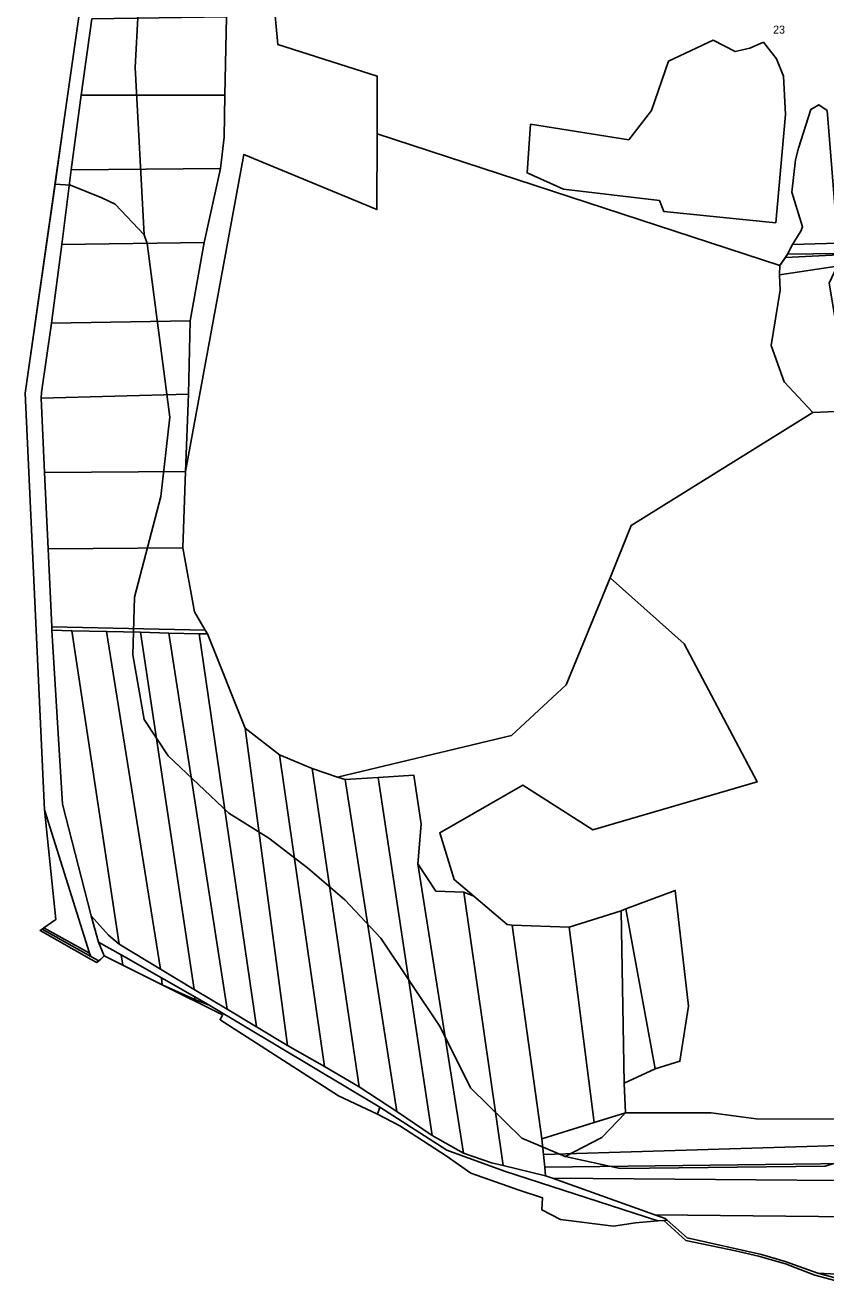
# Model space of a CAD drawing. Extents: x -521261 to -517465, y -1182764 to -1179456.
# Drawn here: x -521261 to -520761, y -1181677 to -1180889 of the extents above; entities that cross this region are included whole.
import ezdxf

# ---------------------------------------------------------------- set-up
doc = ezdxf.new("R2010")
doc.units = 0
for name, color, linetype in [('95560013', 7, 'Continuous'), ('95610013', 7, 'Continuous'), ('95620013', 7, 'Continuous'), ('95640013', 7, 'Continuous'), ('95660013', 7, 'Continuous')]:
    doc.layers.add(name, color=color, linetype=linetype)

msp = doc.modelspace()

# ---------------------------------------------------------------- linework, layer by layer
at = {"layer": '95560013'}
for points in [[(-521219.69, -1180885.08), (-521135.49, -1180884), (-521136.51, -1180932.9), (-521226.29, -1180932.9)], [(-521226.29, -1180932.9), (-521136.51, -1180932.9), (-521137.03, -1180959.08), (-521139.18, -1180978.59), (-521232.52, -1180979.52)], [(-521232.52, -1180979.52), (-521139.18, -1180978.59), (-521149.47, -1181024.96), (-521238.32, -1181026.1)], [(-521238.32, -1181026.1), (-521149.47, -1181024.96), (-521158.27, -1181073.9), (-521244.9, -1181075.28)], [(-521244.9, -1181075.28), (-521158.27, -1181073.9), (-521159.23, -1181119.6), (-521251.27, -1181122.25), (-521251.17, -1181118.7)], [(-521251.27, -1181122.25), (-521159.23, -1181119.6), (-521161.12, -1181167.95), (-521249.31, -1181168.49)], [(-521249.31, -1181168.49), (-521161.12, -1181167.95), (-521162.81, -1181215.7), (-521246.89, -1181216.19)], [(-521246.89, -1181216.19), (-521162.81, -1181215.7), (-521155.45, -1181255.63), (-521148.84, -1181267.14), (-521244.61, -1181265.03)], [(-521244.61, -1181265.03), (-521148.84, -1181267.14), (-521147.36, -1181269.44), (-521152.6, -1181269.31), (-521171.56, -1181268.89), (-521189.16, -1181268.42), (-521210.41, -1181267.89), (-521232.15, -1181267.44), (-521244.55, -1181267.06)], [(-521244.55, -1181267.06), (-521232.15, -1181267.44), (-521202.5, -1181463.17), (-521209.29, -1181457.6), (-521220, -1181445.61), (-521237.91, -1181375.9)], [(-521232.15, -1181267.44), (-521210.41, -1181267.89), (-521176.84, -1181478.98), (-521202.5, -1181463.17)], [(-521210.41, -1181267.89), (-521189.16, -1181268.42), (-521155.74, -1181491.61), (-521176.84, -1181478.98)], [(-521189.16, -1181268.42), (-521171.56, -1181268.89), (-521135.19, -1181503.9), (-521155.74, -1181491.61)], [(-521171.56, -1181268.89), (-521152.6, -1181269.31), (-521116.74, -1181514.95), (-521135.19, -1181503.9)], [(-521152.6, -1181269.31), (-521147.36, -1181269.44), (-521123.91, -1181328.24), (-521097.43, -1181526.5), (-521116.74, -1181514.95)], [(-521123.91, -1181328.24), (-521102.32, -1181344.89), (-521074.33, -1181539.63), (-521097.43, -1181526.5)], [(-521102.32, -1181344.89), (-521082.04, -1181353.53), (-521052.54, -1181552.43), (-521074.33, -1181539.63)], [(-521082.04, -1181353.53), (-521066.19, -1181358.96), (-521061.3, -1181360.4), (-521029.19, -1181567.74), (-521052.54, -1181552.43)], [(-521040.75, -1181359.05), (-521018.46, -1181357.74), (-521013.8, -1181388.33), (-521015.94, -1181413.17), (-520987.49, -1181593.83), (-521006.94, -1181582.72)], [(-521061.3, -1181360.4), (-521040.75, -1181359.05), (-521006.94, -1181582.72), (-521029.19, -1181567.74)], [(-521015.94, -1181413.17), (-521004.72, -1181430.1), (-520987.18, -1181430.86), (-520962.75, -1181601.49), (-520969.91, -1181599.8), (-520987.49, -1181593.83)], [(-520987.18, -1181430.86), (-520981.07, -1181433.26), (-520960.07, -1181451.01), (-520957.12, -1181451.45), (-520938.5, -1181584.87), (-520937.51, -1181594.75), (-520936.72, -1181602.63), (-520936.19, -1181607.92), (-520962.75, -1181601.49)], [(-520921.32, -1181452.64), (-520888.84, -1181442.39), (-520887.02, -1181550.13), (-520886.32, -1181568.63), (-520905.87, -1181574.73)], [(-520957.12, -1181451.45), (-520921.32, -1181452.64), (-520905.87, -1181574.73), (-520938.5, -1181584.87)], [(-521215.46, -1181462.04), (-521201.32, -1181470.02), (-521200.31, -1181476.36), (-521211.86, -1181470.62)], [(-521201.32, -1181470.02), (-521176.23, -1181484.29), (-521175.72, -1181488.6), (-521200.31, -1181476.36)], [(-521176.23, -1181484.29), (-521155.33, -1181496.17), (-521155.23, -1181497.78), (-521175.72, -1181488.6)], [(-521155.23, -1181497.78), (-521145.97, -1181501.62), (-521039.78, -1181565.2), (-521041.22, -1181569.52), (-521065.57, -1181557.94), (-521139.48, -1181510.44), (-521137.91, -1181507.51), (-521175.72, -1181488.6)], [(-521155.33, -1181496.17), (-521145.97, -1181501.62), (-521155.23, -1181497.78)], [(-520886.32, -1181568.63), (-520832.67, -1181568.56), (-520804.67, -1181572.45), (-520752.43, -1181572.59), (-520736.16, -1181561.46), (-520731.92, -1181588.39), (-520937.51, -1181594.75), (-520938.5, -1181584.87), (-520905.87, -1181574.73)], [(-521039.78, -1181565.2), (-520997.8, -1181592.04), (-520961.92, -1181605), (-520865.97, -1181636.11), (-520879.87, -1181637.27), (-520893.72, -1181639.51), (-520926.89, -1181635.27), (-520938.46, -1181629.35), (-520938.04, -1181621.68), (-520952.58, -1181616.94), (-520982.79, -1181606.31), (-520998.32, -1181595.58), (-521027.28, -1181576.76), (-521041.22, -1181569.52)], [(-520937.51, -1181594.75), (-520731.92, -1181588.39), (-520729.78, -1181600.02), (-520936.72, -1181602.63)], [(-520936.72, -1181602.63), (-520729.78, -1181600.02), (-520728.15, -1181611.04), (-520931.87, -1181609.45), (-520936.19, -1181607.92)], [(-520931.87, -1181609.45), (-520728.15, -1181611.04), (-520724.61, -1181633.78), (-520867.79, -1181632.34)], [(-520867.79, -1181632.34), (-520724.61, -1181633.78), (-520720.88, -1181655.89), (-520729.64, -1181670.6), (-520766.06, -1181668.83), (-520786.46, -1181661.6), (-520801.3, -1181657.2), (-520847.78, -1181646.82), (-520860.23, -1181635.71), (-520861.47, -1181634.59)]]:
    msp.add_lwpolyline(points, close=True, dxfattribs=at)
msp.add_lwpolyline([(-520756.08, -1181671.43), (-520766.06, -1181668.83), (-520729.64, -1181670.6)], dxfattribs=at)
at = {"layer": '95610013'}
for points in [[(-520765.33, -1180938.81), (-520760.21, -1180942.51), (-520753.55, -1181025.36), (-520781.8, -1181026.11), (-520776.76, -1181017.76), (-520775.73, -1181015.12), (-520782.22, -1180993.52), (-520780.05, -1180973.32), (-520778.12, -1180965.89), (-520770.41, -1180941.78)], [(-520754, -1181039.73), (-520758.98, -1181050.37), (-520745.59, -1181130), (-520769.1, -1181131.19), (-520787.16, -1181111.94), (-520795.31, -1181089.15), (-520789.59, -1181054.58), (-520789.95, -1181044.99)]]:
    msp.add_lwpolyline(points, close=True, dxfattribs=at)
at = {"layer": '95620013'}
for points in [[(-521134.59, -1180840.77), (-521090.43, -1180838.7), (-521107.32, -1180858.01), (-521103.44, -1180901.21), (-521041.31, -1180920.9), (-521041.32, -1180957.03), (-521041.57, -1181004.34), (-521124.61, -1180969.86), (-521161.12, -1181167.95), (-521159.23, -1181119.6), (-521158.27, -1181073.9), (-521149.47, -1181024.96), (-521139.18, -1180978.59), (-521137.03, -1180959.08), (-521136.51, -1180932.9), (-521135.49, -1180884)], [(-520800.05, -1180899.82), (-520791.92, -1180910.17), (-520787.44, -1180920.88), (-520786.19, -1180944.93), (-520792.33, -1181012.6), (-520862.28, -1181005.5), (-520865.02, -1180998.7), (-520924.89, -1180991.65), (-520947.73, -1180981.31), (-520945.52, -1180951.06), (-520884.15, -1180960.85), (-520870, -1180942.37), (-520859.37, -1180911.64), (-520831.42, -1180898.43), (-520817.63, -1180905.6), (-520808.63, -1180903.54)], [(-520800.05, -1180899.82), (-520808.63, -1180903.54), (-520817.63, -1180905.6), (-520831.42, -1180898.43), (-520859.37, -1180911.64), (-520870, -1180942.37), (-520884.15, -1180960.85), (-520945.52, -1180951.06), (-520947.73, -1180981.31), (-520924.89, -1180991.65), (-520865.02, -1180998.7), (-520862.28, -1181005.5), (-520792.33, -1181012.6), (-520786.19, -1180944.93), (-520787.44, -1180920.88), (-520791.92, -1180910.17)], [(-521041.57, -1181004.34), (-521041.32, -1180957.03), (-520789.78, -1181039.28), (-520789.95, -1181044.99), (-520789.59, -1181054.58), (-520795.31, -1181089.15), (-520787.16, -1181111.94), (-520769.1, -1181131.19), (-520882.71, -1181201.62), (-520895.83, -1181234.46), (-520923.27, -1181301.34), (-520957.49, -1181332.89), (-521066.19, -1181358.96), (-521082.04, -1181353.53), (-521102.32, -1181344.89), (-521123.91, -1181328.24), (-521147.36, -1181269.44), (-521148.84, -1181267.14), (-521155.45, -1181255.63), (-521162.81, -1181215.7), (-521161.12, -1181167.95), (-521124.61, -1180969.86)], [(-520895.83, -1181234.46), (-520849.55, -1181275.69), (-520803.91, -1181361.75), (-520906.55, -1181391.93), (-520950.46, -1181363.92), (-521002.26, -1181393.66), (-520993.19, -1181422.88), (-520981.07, -1181433.26), (-520987.18, -1181430.86), (-521004.72, -1181430.1), (-521015.94, -1181413.17), (-521013.8, -1181388.33), (-521018.46, -1181357.74), (-521040.75, -1181359.05), (-521061.3, -1181360.4), (-521066.19, -1181358.96), (-520957.49, -1181332.89), (-520923.27, -1181301.34)], [(-520886.09, -1181441.09), (-520855.1, -1181429.72), (-520846.82, -1181502), (-520852.26, -1181536.38), (-520867.63, -1181541.1)], [(-520888.84, -1181442.39), (-520886.09, -1181441.09), (-520867.63, -1181541.1), (-520887.02, -1181550.13)]]:
    msp.add_lwpolyline(points, close=True, dxfattribs=at)
for points in [[(-520760.21, -1180942.51), (-520765.33, -1180938.81), (-520770.41, -1180941.78), (-520778.12, -1180965.89), (-520780.05, -1180973.32), (-520782.22, -1180993.52), (-520775.73, -1181015.12), (-520776.76, -1181017.76), (-520781.8, -1181026.11), (-520784.95, -1181032.19), (-520789.78, -1181039.28), (-521041.32, -1180957.03), (-521041.31, -1180920.9), (-521103.44, -1180901.21), (-521107.32, -1180858.01)], [(-520752.43, -1181572.59), (-520804.67, -1181572.45), (-520832.67, -1181568.56), (-520886.32, -1181568.63), (-520887.02, -1181550.13), (-520867.63, -1181541.1), (-520852.26, -1181536.38), (-520846.82, -1181502), (-520855.1, -1181429.72), (-520886.09, -1181441.09), (-520888.84, -1181442.39), (-520921.32, -1181452.64), (-520957.12, -1181451.45), (-520960.07, -1181451.01), (-520981.07, -1181433.26), (-520993.19, -1181422.88), (-521002.26, -1181393.66), (-520950.46, -1181363.92), (-520906.55, -1181391.93), (-520803.91, -1181361.75), (-520849.55, -1181275.69), (-520895.83, -1181234.46), (-520882.71, -1181201.62), (-520769.1, -1181131.19), (-520745.59, -1181130)]]:
    msp.add_lwpolyline(points, dxfattribs=at)
at = {"layer": '95640013'}
for points in [[(-521219.69, -1180885.08), (-521226.29, -1180932.9), (-521232.52, -1180979.52), (-521238.32, -1181026.1), (-521244.9, -1181075.28), (-521251.17, -1181118.7), (-521251.27, -1181122.25), (-521249.31, -1181168.49), (-521246.89, -1181216.19), (-521244.61, -1181265.03), (-521244.55, -1181267.06), (-521237.91, -1181375.9), (-521220, -1181445.61), (-521215.46, -1181462.04), (-521211.86, -1181470.62), (-521214.11, -1181472.65), (-521215.29, -1181473.73), (-521220.37, -1181470.88), (-521221.03, -1181468.82), (-521249.27, -1181379.35), (-521261.28, -1181118.92), (-521236.44, -1180945.21), (-521211.68, -1180771.41)], [(-520752.89, -1181031.72), (-520784.95, -1181032.19), (-520781.8, -1181026.11), (-520753.55, -1181025.36)], [(-520742.99, -1181676.7), (-520767.86, -1181669.98), (-520786.31, -1181662.97), (-520803.11, -1181658.11), (-520817.41, -1181654.92), (-520848.48, -1181648.48), (-520862.22, -1181635.85), (-520860.23, -1181635.71), (-520847.78, -1181646.82), (-520801.3, -1181657.2), (-520786.46, -1181661.6), (-520766.06, -1181668.83), (-520756.08, -1181671.43)]]:
    msp.add_lwpolyline(points, dxfattribs=at)
for points in [[(-520737.28, -1181031.47), (-520735.59, -1181031.57), (-520734.93, -1181038.06), (-520734.68, -1181044.73), (-520754, -1181039.73), (-520789.95, -1181044.99), (-520789.78, -1181039.28), (-520784.95, -1181032.19), (-520752.89, -1181031.72)], [(-521249.27, -1181379.35), (-521221.03, -1181468.82), (-521249.55, -1181452.99), (-521242.23, -1181447.88)], [(-521209.29, -1181457.6), (-521202.5, -1181463.17), (-521176.84, -1181478.98), (-521155.74, -1181491.61), (-521135.19, -1181503.9), (-521116.74, -1181514.95), (-521097.43, -1181526.5), (-521074.33, -1181539.63), (-521052.54, -1181552.43), (-521029.19, -1181567.74), (-521006.94, -1181582.72), (-520987.49, -1181593.83), (-520969.91, -1181599.8), (-520962.75, -1181601.49), (-520936.19, -1181607.92), (-520931.87, -1181609.45), (-520867.79, -1181632.34), (-520861.47, -1181634.59), (-520860.23, -1181635.71), (-520862.22, -1181635.85), (-520865.97, -1181636.11), (-520961.92, -1181605), (-520997.8, -1181592.04), (-521039.78, -1181565.2), (-521145.97, -1181501.62), (-521155.33, -1181496.17), (-521176.23, -1181484.29), (-521201.32, -1181470.02), (-521215.46, -1181462.04), (-521220, -1181445.61)], [(-521250.74, -1181453.83), (-521220.37, -1181470.88), (-521215.29, -1181473.73), (-521216.62, -1181474.75), (-521220.04, -1181472.8), (-521251.97, -1181454.65)], [(-521249.55, -1181452.99), (-521221.03, -1181468.82), (-521220.37, -1181470.88), (-521250.74, -1181453.83)]]:
    msp.add_lwpolyline(points, close=True, dxfattribs=at)
at = {"layer": '95660013'}
for points in [[(-521189.5, -1180857), (-521192.5, -1180915.5), (-521187, -1181020), (-521205, -1181001), (-521213.5, -1180997), (-521233, -1180989), (-521242.62, -1180988.46), (-521236.44, -1180945.21), (-521211.68, -1180771.41)], [(-521135.49, -1180884), (-521136.51, -1180932.9), (-521137.03, -1180959.08), (-521139.18, -1180978.59), (-521149.47, -1181024.96), (-521158.27, -1181073.9), (-521159.23, -1181119.6), (-521161.12, -1181167.95), (-521162.81, -1181215.7), (-521155.45, -1181255.63), (-521148.84, -1181267.14), (-521147.36, -1181269.44), (-521123.91, -1181328.24), (-521102.32, -1181344.89), (-521082.04, -1181353.53), (-521066.19, -1181358.96), (-521061.3, -1181360.4), (-521040.75, -1181359.05), (-521018.46, -1181357.74), (-521013.8, -1181388.33), (-521015.94, -1181413.17), (-521004.72, -1181430.1), (-520987.18, -1181430.86), (-520981.07, -1181433.26), (-520960.07, -1181451.01), (-520957.12, -1181451.45), (-520921.32, -1181452.64), (-520888.84, -1181442.39), (-520887.02, -1181550.13), (-520886.32, -1181568.63), (-520901, -1181584), (-520924, -1181596), (-520951, -1181584.5), (-520983, -1181553), (-521002, -1181515), (-521039, -1181459.5), (-521061.5, -1181435.5), (-521085, -1181415.5), (-521109, -1181397), (-521134, -1181381.5), (-521172, -1181345.5), (-521187, -1181323), (-521194, -1181282.5), (-521193, -1181246.5), (-521176.5, -1181183.5), (-521171, -1181134), (-521185, -1181025.5), (-521187, -1181020), (-521192.5, -1180915.5), (-521189.5, -1180857)], [(-520752.43, -1181572.59), (-520804.67, -1181572.45), (-520832.67, -1181568.56), (-520886.32, -1181568.63), (-520887.02, -1181550.13), (-520888.84, -1181442.39), (-520921.32, -1181452.64), (-520957.12, -1181451.45), (-520960.07, -1181451.01), (-520981.07, -1181433.26), (-520987.18, -1181430.86), (-521004.72, -1181430.1), (-521015.94, -1181413.17), (-521013.8, -1181388.33), (-521018.46, -1181357.74), (-521040.75, -1181359.05), (-521061.3, -1181360.4), (-521066.19, -1181358.96), (-521082.04, -1181353.53), (-521102.32, -1181344.89), (-521123.91, -1181328.24), (-521147.36, -1181269.44), (-521148.84, -1181267.14), (-521155.45, -1181255.63), (-521162.81, -1181215.7), (-521161.12, -1181167.95), (-521159.23, -1181119.6), (-521158.27, -1181073.9), (-521149.47, -1181024.96), (-521139.18, -1180978.59), (-521137.03, -1180959.08), (-521136.51, -1180932.9), (-521135.49, -1180884)], [(-520760.21, -1180942.51), (-520765.33, -1180938.81), (-520770.41, -1180941.78), (-520778.12, -1180965.89), (-520780.05, -1180973.32), (-520782.22, -1180993.52), (-520775.73, -1181015.12), (-520776.76, -1181017.76), (-520781.8, -1181026.11), (-520784.95, -1181032.19), (-520786.29, -1181034.16), (-520789.78, -1181039.28), (-520789.95, -1181044.99), (-520789.59, -1181054.58), (-520795.31, -1181089.15), (-520787.16, -1181111.94), (-520769.1, -1181131.19), (-520745.59, -1181130)], [(-520740.5, -1181032), (-520786.29, -1181034.16), (-520784.95, -1181032.19), (-520781.8, -1181026.11), (-520776.76, -1181017.76), (-520775.73, -1181015.12), (-520782.22, -1180993.52), (-520780.05, -1180973.32), (-520778.12, -1180965.89), (-520770.41, -1180941.78), (-520765.33, -1180938.81), (-520760.21, -1180942.51)], [(-520742.99, -1181676.7), (-520767.86, -1181669.98), (-520786.31, -1181662.97), (-520803.11, -1181658.11), (-520817.41, -1181654.92), (-520848.48, -1181648.48), (-520862.22, -1181635.85), (-520865.97, -1181636.11), (-520879.87, -1181637.27), (-520893.72, -1181639.51), (-520926.89, -1181635.27), (-520938.46, -1181629.35), (-520938.04, -1181621.68), (-520952.58, -1181616.94), (-520982.79, -1181606.31), (-520998.32, -1181595.58), (-521027.28, -1181576.76), (-521041.22, -1181569.52), (-521065.57, -1181557.94), (-521139.48, -1181510.44), (-521137.91, -1181507.51), (-521175.72, -1181488.6), (-521200.31, -1181476.36), (-521211.86, -1181470.62), (-521214.11, -1181472.65), (-521215.29, -1181473.73), (-521216.62, -1181474.75), (-521220.04, -1181472.8), (-521251.97, -1181454.65), (-521250.74, -1181453.83), (-521249.55, -1181452.99), (-521242.23, -1181447.88), (-521249.27, -1181379.35), (-521261.28, -1181118.92), (-521242.62, -1180988.46), (-521233, -1180989), (-521213.5, -1180997), (-521205, -1181001), (-521187, -1181020), (-521185, -1181025.5), (-521171, -1181134), (-521176.5, -1181183.5), (-521193, -1181246.5), (-521194, -1181282.5), (-521187, -1181323), (-521172, -1181345.5), (-521134, -1181381.5), (-521109, -1181397), (-521085, -1181415.5), (-521061.5, -1181435.5), (-521039, -1181459.5), (-521002, -1181515), (-520983, -1181553), (-520951, -1181584.5), (-520924, -1181596), (-520889.5, -1181603.5), (-520761.5, -1181602), (-520736.5, -1181594.5)], [(-520745.59, -1181130), (-520769.1, -1181131.19), (-520787.16, -1181111.94), (-520795.31, -1181089.15), (-520789.59, -1181054.58), (-520789.95, -1181044.99), (-520789.78, -1181039.28), (-520786.29, -1181034.16), (-520740.5, -1181032)], [(-520736.5, -1181594.5), (-520761.5, -1181602), (-520889.5, -1181603.5), (-520924, -1181596), (-520901, -1181584), (-520886.32, -1181568.63), (-520832.67, -1181568.56), (-520804.67, -1181572.45), (-520752.43, -1181572.59)]]:
    msp.add_lwpolyline(points, dxfattribs=at)

# ---------------------------------------------------------------- texts
msp.add_text('23', height=5, rotation=360, dxfattribs=at).set_placement((-520794.01, -1180894.4))

doc.saveas('drawing.dxf')
